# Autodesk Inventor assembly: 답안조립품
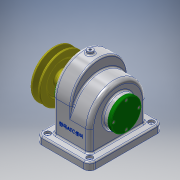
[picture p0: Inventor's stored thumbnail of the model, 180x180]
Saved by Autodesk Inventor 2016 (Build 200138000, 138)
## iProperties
Created: 2017-11
Part Number: 답안조립품
Material: 일반
Document SubType Name: Assembly
Designer: USER
Author: USER
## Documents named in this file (14)
- C:\Users\USER\Desktop\471107V1036\답안조립품.iam
- C:\Users\USER\Desktop\471107V1036\본체.ipt
- C:\Users\USER\Desktop\471107V1036\V-벨트풀리.ipt
- C:\Users\USER\Desktop\471107V1036\뒤커버.ipt
- C:\Users\USER\Desktop\471107V1036\멈춤나사 - M4 x 10.ipt
- 멈춤나사 - M4 x 10.ipt
- C:\Users\USER\Desktop\471107V1036\베어링 6002.ipt
- C:\Users\USER\Desktop\471107V1036\볼트 M3 x 8.ipt
- C:\Users\USER\Desktop\471107V1036\스퍼기어.ipt
- C:\Users\USER\Desktop\471107V1036\앞커버.ipt
- C:\Users\USER\Desktop\471107V1036\오일 실 15 30 7.ipt
- C:\Users\USER\Desktop\471107V1036\축.ipt
- C:\Users\USER\Desktop\471107V1036\키 - 5 x 5 x 18.ipt
- C:\Users\USER\Desktop\471107V1036\키 - 6 x 6 x 22.ipt
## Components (1 placed, 1 different names)
1. V-벨트풀리:1
